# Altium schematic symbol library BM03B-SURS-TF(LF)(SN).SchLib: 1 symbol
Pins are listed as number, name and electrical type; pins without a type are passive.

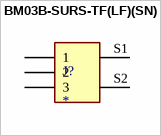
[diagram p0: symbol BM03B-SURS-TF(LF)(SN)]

## BM03B-SURS-TF(LF)(SN)
designator J?
Conn Shrouded Header (4 Sides) HDR 3 POS 0.8mm Solder ST SMD T/R; MF: JST Corporation; MP: BM03B-SURS-TF (LF)(SN)
footprint JST_BM03B-SURS-TF(LF)(SN)
pins: 1, 2, 3, S1 SHIELD, S2 SHIELD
